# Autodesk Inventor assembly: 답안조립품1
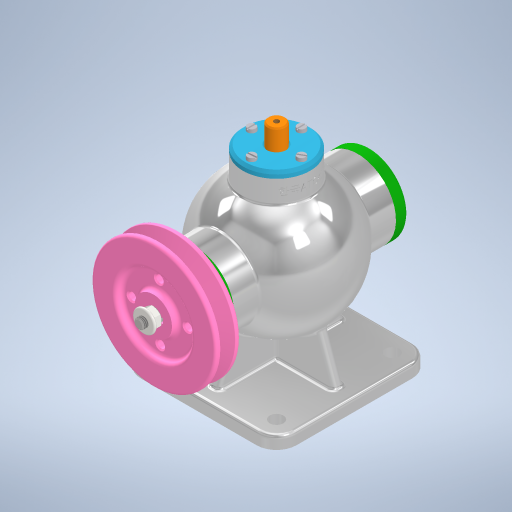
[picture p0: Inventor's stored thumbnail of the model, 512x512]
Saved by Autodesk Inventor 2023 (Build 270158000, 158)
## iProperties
Created: 2023-07
Part Number: 답안조립품1
Document SubType Name: Assembly
Designer: Owner
Author: Owner
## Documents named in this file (16)
- C:\Users\Owner\Desktop\730711V1006\답안조립품.iam
- C:\Users\Owner\Desktop\730711V1006\본체.ipt
- C:\Users\Owner\Desktop\730711V1006\편심축.ipt
- C:\Users\Owner\Desktop\730711V1006\칼라.ipt
- C:\Users\Owner\Desktop\730711V1006\베어링- 6202.ipt
- KS B 2023 - 6202 - 15 x 35 x 11 - 7.8.ipt
- C:\Users\Owner\Desktop\730711V1006\앞커버.ipt
- C:\Users\Owner\Desktop\730711V1006\뒤커버.ipt
- C:\Users\Owner\Desktop\730711V1006\오일실 15 30 7.ipt
- C:\Users\Owner\Desktop\730711V1006\V-벨트풀리.ipt
- C:\Users\Owner\Desktop\730711V1006\키 4 x 4 x 12.ipt
- C:\Users\Owner\Desktop\730711V1006\너트 M8.ipt
- C:\Users\Owner\Desktop\730711V1006\슬라이드.ipt
- C:\Users\Owner\Desktop\730711V1006\상부커버.ipt
- C:\Users\Owner\Desktop\730711V1006\볼트 M4 x 16.ipt
- C:\Users\Owner\Desktop\730711V1006\볼트 M4 x 12.ipt
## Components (15 placed, 4 different names)
1. KS B 2023 - 6202 - 15 x 35 x 11 - 7.8:1
2. KS B 2023 - 6202 - 15 x 35 x 11 - 7.8:2
3. V-벨트풀리:1
4. KS B 1021 - 에 따름 ISO 1207 - 미터 A  M 4 x 12:1
5. KS B 1021 - 에 따름 ISO 1207 - 미터 A  M 4 x 12:2
6. KS B 1021 - 에 따름 ISO 1207 - 미터 A  M 4 x 12:3
7. KS B 1021 - 에 따름 ISO 1207 - 미터 A  M 4 x 12:4
8. ISO 4762 M4 x 16:1
9. ISO 4762 M4 x 16:2
10. ISO 4762 M4 x 16:3
11. ISO 4762 M4 x 16:4
12. ISO 4762 M4 x 16:5
13. ISO 4762 M4 x 16:6
14. ISO 4762 M4 x 16:7
15. ISO 4762 M4 x 16:8
